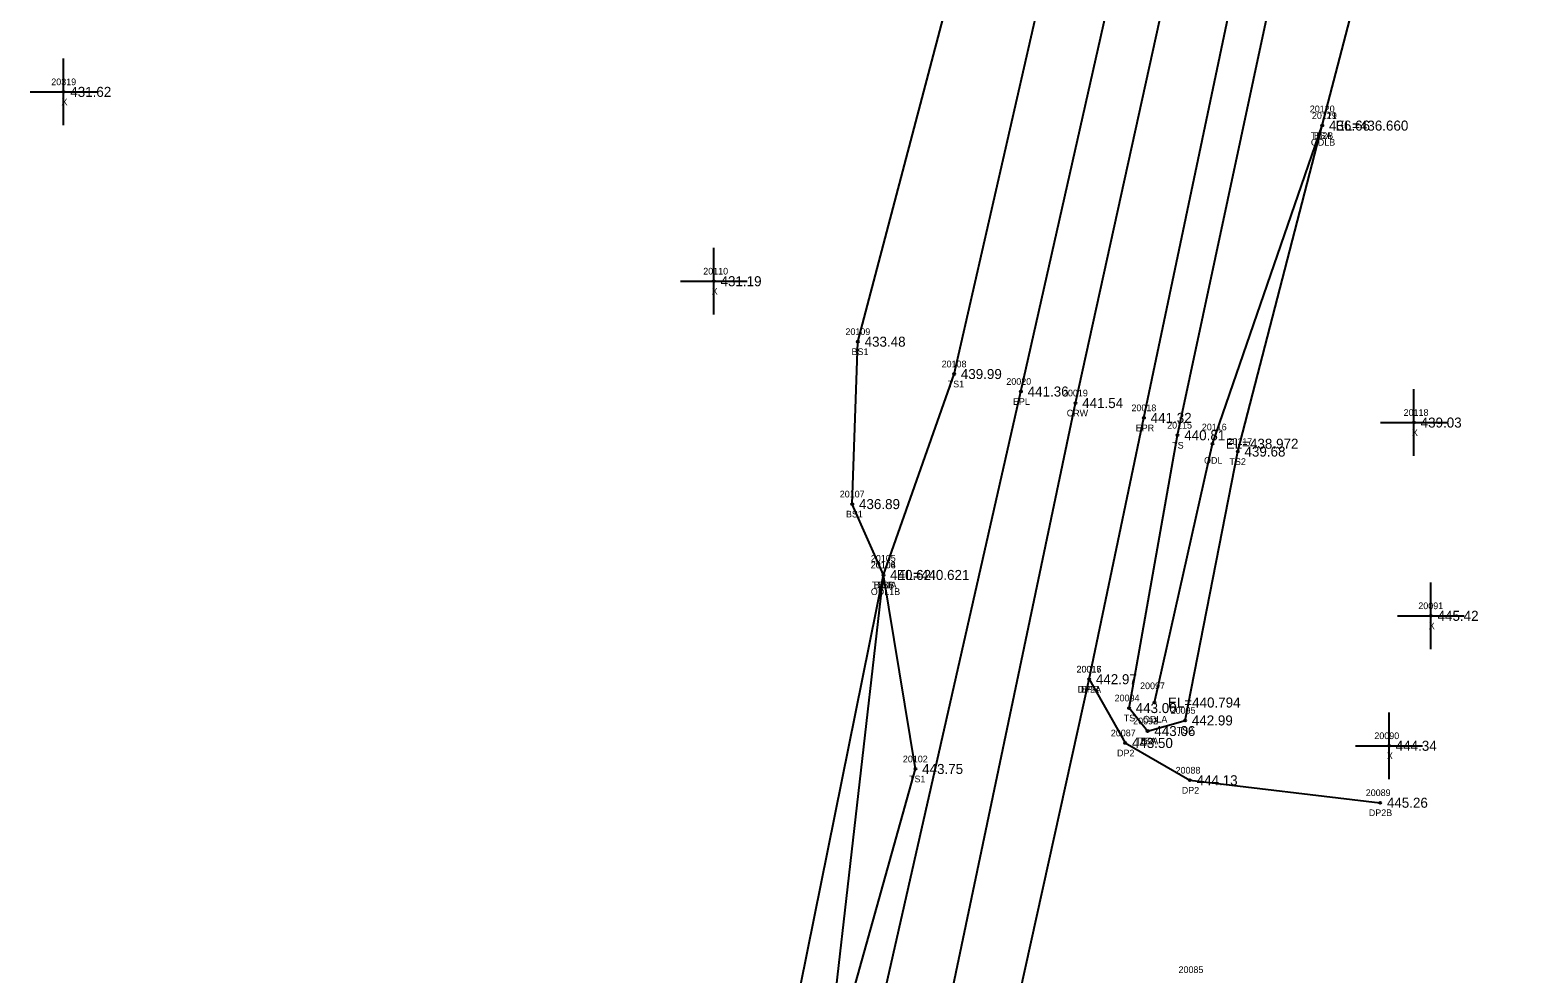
# Model space of a CAD drawing. Extents: x 1755707 to 1756750, y 975854 to 977363.
# Drawn here: x 1755994.4 to 1756220.1, y 976284.1 to 976425.4 of the extents above; entities that cross this region are included whole.
import ezdxf

# ---------------------------------------------------------------- set-up
doc = ezdxf.new("R2010")
doc.units = 0
for name, color, linetype in [('RD_DTM_BkLn1', 7, 'Continuous'), ('RD_DTM_BkLn2', 7, 'Continuous'), ('RD_DTM_BkLn_txCode', 7, 'Continuous'), ('RD_EX_Driveway', 7, 'Continuous'), ('RD_EX_Driveway_txCode', 7, 'Continuous'), ('RD_EX_H2O', 7, 'Continuous'), ('RD_EX_H2O_txCode', 7, 'Continuous'), ('RD_EX_Misc', 7, 'Continuous'), ('RD_EX_Misc_txCode', 7, 'Continuous'), ('RD_EX_Road', 7, 'Continuous'), ('RD_EX_Road_txCode', 7, 'Continuous'), ('RD_EX_TX_Driveway_ELEV', 7, 'Continuous'), ('RD_EX_TX_H2O_ELEV', 7, 'Continuous'), ('RD_EX_TX_Misc_ELEV', 7, 'Continuous'), ('RD_EX_TX_Road_ELEV', 7, 'Continuous'), ('RD_HC_Survey_ELEV', 7, 'Continuous'), ('RD_HC_Survey_txCode', 7, 'Continuous'), ('RD_SMD_Locator', 7, 'Continuous')]:
    doc.layers.add(name, color=color, linetype=linetype)

msp = doc.modelspace()

# ---------------------------------------------------------------- linework, layer by layer
at = {"layer": 'RD_DTM_BkLn1'}
msp.add_lwpolyline([(1756046.01, 975873.44), (1756066.9, 975971.26), (1756086.38, 976067.89), (1756106.72, 976164.82), (1756129.4, 976267.02), (1756150.88, 976369.58), (1756171.91, 976465.4), (1756192.77, 976559.17)], dxfattribs=at)
at = {"layer": 'RD_DTM_BkLn2'}
for points in [[(1756122.13, 976343.84), (1756117.48, 976354.45), (1756118.32, 976378.77), (1756143.1, 976472.88), (1756166.57, 976563.07), (1756180.02, 976571)], [(1756187.82, 976411.13), (1756200.77, 976460.92), (1756220.08, 976553.81), (1756210.33, 976564.23), (1756180.02, 976571)], [(1756033.66, 975875.52), (1756053.42, 975974.8), (1756049.94, 976015.39), (1756032.6, 976091.06), (1756047.31, 976093.5), (1756074.57, 976074.24), (1756094.56, 976168.06), (1756114.78, 976271.24), (1756126.93, 976314.79), (1756122.13, 976343.84), (1756132.72, 976373.93), (1756154.73, 976470.38), (1756169.17, 976546.64), (1756175.23, 976558.93), (1756179.42, 976561.34)], [(1756161.68, 976320.47), (1756158.89, 976323.91), (1756166.16, 976364.76), (1756187.03, 976462.63), (1756209.82, 976550.53), (1756207.19, 976554.82)], [(1756161.68, 976320.47), (1756167.29, 976322.06), (1756175.17, 976362.32), (1756187.82, 976411.13)], [(1756042.43, 976143.55), (1756047.59, 976114.3), (1756072.35, 976091.95), (1756089.57, 976168.97), (1756107.62, 976271.94), (1756122.13, 976343.84)]]:
    msp.add_lwpolyline(points, dxfattribs=at)
at = {"layer": 'RD_EX_Driveway'}
msp.add_lwpolyline([(1756152.93, 976328.23), (1756158.32, 976318.68), (1756168.01, 976313.1), (1756196.48, 976309.73)], dxfattribs=at)
at = {"layer": 'RD_EX_H2O'}
for points in [[(1756162.71, 976324.74), (1756171.37, 976363.49), (1756187.82, 976411.13)], [(1756030.87, 975876.19), (1756050.83, 975975.22), (1756043.54, 976014.53), (1756027.41, 976122.36), (1756072.81, 976080.09), (1756091.83, 976168.45), (1756113.86, 976271.37), (1756122.13, 976343.84)]]:
    msp.add_lwpolyline(points, dxfattribs=at)
at = {"layer": 'RD_EX_Misc'}
for p, q in [((1755999.44, 976411.18), (1755999.44, 976421.18)), ((1755994.44, 976416.18), (1756004.44, 976416.18)), ((1756096.76, 976382.83), (1756096.76, 976392.83)), ((1756091.76, 976387.83), (1756101.76, 976387.83)), ((1756201.54, 976361.66), (1756201.54, 976371.66)), ((1756196.54, 976366.66), (1756206.54, 976366.66)), ((1756204.07, 976332.72), (1756204.07, 976342.72)), ((1756199.07, 976337.72), (1756209.07, 976337.72)), ((1756197.81, 976313.26), (1756197.81, 976323.26)), ((1756192.81, 976318.26), (1756202.81, 976318.26))]:
    msp.add_line(p, q, dxfattribs=at)
at = {"layer": 'RD_EX_Road'}
for points in [[(1756035.19, 975875.88), (1756056.24, 975973.07), (1756076.6, 976069.51), (1756097.1, 976167.18), (1756119.62, 976269.35), (1756142.72, 976371.31), (1756164.37, 976467.45), (1756183.15, 976561.19), (1756192.77, 976559.17)], [(1756056.66, 975870.37), (1756077.66, 975967.46), (1756097.63, 976065.09), (1756118.05, 976161.7), (1756139.04, 976265.41), (1756152.93, 976328.23), (1756161.13, 976367.36), (1756181.28, 976463.3), (1756202.22, 976557.13), (1756192.77, 976559.17)]]:
    msp.add_lwpolyline(points, dxfattribs=at)
at = {"layer": 'RD_SMD_Locator'}
for centre in [(1755999.44, 976416.18), (1756187.82, 976411.13), (1756187.82, 976411.13), (1756187.82, 976411.13), (1756096.76, 976387.83), (1756118.32, 976378.77), (1756132.72, 976373.93), (1756142.72, 976371.31), (1756150.88, 976369.58), (1756161.13, 976367.36), (1756201.54, 976366.66), (1756166.16, 976364.76), (1756171.37, 976363.49), (1756175.17, 976362.32), (1756117.48, 976354.45), (1756122.13, 976343.84), (1756122.13, 976343.84), (1756122.13, 976343.84), (1756122.13, 976343.84), (1756204.07, 976337.72), (1756152.93, 976328.23), (1756152.93, 976328.23), (1756162.71, 976324.74), (1756158.89, 976323.91), (1756167.29, 976322.06), (1756161.68, 976320.47), (1756161.68, 976320.47), (1756158.32, 976318.68), (1756197.81, 976318.26), (1756126.93, 976314.79), (1756168.01, 976313.1), (1756196.48, 976309.73)]:
    msp.add_circle(centre, 0.15, dxfattribs=at)

# ---------------------------------------------------------------- texts
at = {"layer": 'RD_DTM_BkLn_txCode'}
for s, p in [('20119', (1756186.27, 976412.13)), ('20121', (1756186.27, 976412.13)), ('TS2B', (1756186.11, 976409.13)), ('BSA', (1756186.56, 976409.13)), ('20109', (1756116.45, 976379.77)), ('BS1', (1756117.37, 976376.77)), ('20108', (1756130.85, 976374.93)), ('TS1', (1756131.76, 976371.93)), ('20115', (1756164.6, 976365.76)), ('TS', (1756165.36, 976362.76)), ('20117', (1756173.62, 976363.32)), ('TS2', (1756173.93, 976360.32)), ('20107', (1756115.6, 976355.45)), ('BS1', (1756116.53, 976352.45)), ('20106', (1756120.23, 976344.84)), ('20103', (1756120.26, 976344.84)), ('20104', (1756120.26, 976344.84)), ('TS3B', (1756120.41, 976341.84)), ('BS1A', (1756120.7, 976341.84)), ('TS1', (1756121.17, 976341.84)), ('20094', (1756156.74, 976324.91)), ('TS', (1756158.1, 976321.91)), ('20092', (1756159.52, 976321.47)), ('20093', (1756159.52, 976321.47)), ('20095', (1756165.13, 976323.06)), ('TS2', (1756166.05, 976320.06)), ('TS2A', (1756159.94, 976318.47)), ('TSA', (1756160.39, 976318.47)), ('20102', (1756125.05, 976315.79)), ('TS1', (1756125.97, 976312.79))]:
    msp.add_text(s, height=1, dxfattribs=at).set_placement(p)
at = {"layer": 'RD_EX_Driveway_txCode'}
for s, p in [('20017', (1756151.05, 976329.23)), ('DP2A', (1756151.21, 976326.23)), ('20087', (1756156.17, 976319.68)), ('DP2', (1756157.1, 976316.68)), ('20088', (1756165.86, 976314.1)), ('DP2', (1756166.79, 976311.1)), ('20089', (1756194.32, 976310.73)), ('DP2B', (1756194.78, 976307.73)), ('20085', (1756166.3, 976284.23))]:
    msp.add_text(s, height=1, dxfattribs=at).set_placement(p)
at = {"layer": 'RD_EX_H2O_txCode'}
for s, p in [('20120', (1756185.95, 976413.13)), ('ODLB', (1756186.11, 976408.13)), ('20116', (1756169.79, 976365.49)), ('ODL', (1756170.12, 976360.49)), ('20105', (1756120.26, 976345.84)), ('ODL1B', (1756120.25, 976340.84)), ('20097', (1756160.55, 976326.74)), ('ODLA', (1756160.98, 976321.74))]:
    msp.add_text(s, height=1, dxfattribs=at).set_placement(p)
at = {"layer": 'RD_EX_Misc_txCode'}
for s, p in [('20319', (1755997.6, 976417.18)), ('X', (1755999.12, 976414.18)), ('20110', (1756095.17, 976388.83)), ('X', (1756096.44, 976385.83)), ('20118', (1756199.99, 976367.66)), ('X', (1756201.23, 976364.66)), ('20091', (1756202.19, 976338.72)), ('X', (1756203.75, 976335.72)), ('20090', (1756195.61, 976319.26)), ('X', (1756197.49, 976316.26))]:
    msp.add_text(s, height=1, dxfattribs=at).set_placement(p)
at = {"layer": 'RD_EX_Road_txCode'}
for s, p in [('20020', (1756140.53, 976372.31)), ('EPL', (1756141.52, 976369.31)), ('20018', (1756159.26, 976368.36)), ('EPR', (1756159.9, 976365.36)), ('20016', (1756151.03, 976329.23)), ('EPR', (1756151.7, 976326.23))]:
    msp.add_text(s, height=1, dxfattribs=at).set_placement(p)
at = {"layer": 'RD_EX_TX_Driveway_ELEV'}
for s, p in [('442.97', (1756153.93, 976327.48)), ('443.50', (1756159.32, 976317.93)), ('444.13', (1756169.01, 976312.35)), ('445.26', (1756197.48, 976308.98))]:
    msp.add_text(s, height=1.5, dxfattribs=at).set_placement(p)
at = {"layer": 'RD_EX_TX_H2O_ELEV'}
for s, p in [('EL=436.660', (1756189.82, 976410.38)), ('EL=438.972', (1756173.37, 976362.74)), ('EL=440.621', (1756124.13, 976343.09)), ('EL=440.794', (1756164.71, 976323.99))]:
    msp.add_text(s, height=1.5, dxfattribs=at).set_placement(p)
at = {"layer": 'RD_EX_TX_Misc_ELEV'}
for s, p in [('431.62', (1756000.44, 976415.43)), ('436.66', (1756188.82, 976410.38)), ('436.66', (1756188.82, 976410.38)), ('431.19', (1756097.76, 976387.08)), ('433.48', (1756119.32, 976378.02)), ('439.99', (1756133.72, 976373.18)), ('439.03', (1756202.54, 976365.91)), ('440.81', (1756167.16, 976364.01)), ('439.68', (1756176.17, 976361.57)), ('436.89', (1756118.48, 976353.7)), ('440.62', (1756123.13, 976343.09)), ('440.62', (1756123.13, 976343.09)), ('440.62', (1756123.13, 976343.09)), ('445.42', (1756205.07, 976336.97)), ('443.00', (1756159.89, 976323.16)), ('442.99', (1756168.29, 976321.31)), ('443.06', (1756162.68, 976319.72)), ('443.06', (1756162.68, 976319.72)), ('444.34', (1756198.81, 976317.51)), ('443.75', (1756127.93, 976314.04))]:
    msp.add_text(s, height=1.5, dxfattribs=at).set_placement(p)
at = {"layer": 'RD_EX_TX_Road_ELEV'}
for s, p in [('441.36', (1756143.72, 976370.56)), ('441.32', (1756162.13, 976366.61)), ('442.97', (1756153.93, 976327.48))]:
    msp.add_text(s, height=1.5, dxfattribs=at).set_placement(p)
at = {"layer": 'RD_HC_Survey_ELEV'}
msp.add_text('441.54', height=1.5, dxfattribs=at).set_placement((1756151.88, 976368.83))
at = {"layer": 'RD_HC_Survey_txCode'}
for s, p in [('20019', (1756149.01, 976370.58)), ('CRW', (1756149.57, 976367.58))]:
    msp.add_text(s, height=1, dxfattribs=at).set_placement(p)

doc.saveas('drawing.dxf')
